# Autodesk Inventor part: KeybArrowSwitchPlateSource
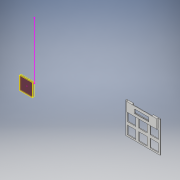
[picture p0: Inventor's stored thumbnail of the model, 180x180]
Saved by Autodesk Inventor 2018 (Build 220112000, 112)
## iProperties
Created: 2017-10
Part Number: KeybArrowSwitchPlateSource
Material: Generic
Document SubType Name: Modeling
Designer: Buddy
Density: 1 g/cm^3
Appearance: Default
Author: Buddy
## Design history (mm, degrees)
sketch "File Was"
  geometry: L1 (222.827, 62.893)-(216.827, 62.893); L2 (168.201, 27.319)-(182.201, 27.319); L3 (182.201, 27.319)-(182.201, 13.32); L4 (182.201, 13.32)-(168.201, 13.32); L5 (168.201, 13.32)-(168.201, 27.319); L6 (187.251, 27.319)-(201.251, 27.319); L7 (201.251, 27.319)-(201.251, 13.32); L8 (201.251, 13.32)-(187.251, 13.32); L9 (187.251, 13.32)-(187.251, 27.319); L10 (206.301, 13.32)-(206.301, 27.319); L11 (220.301, 27.319)-(220.301, 13.32); L12 (220.301, 13.32)-(206.301, 13.32); L13 (206.301, 27.319)-(220.301, 27.319); L14 (201.251, 46.369)-(201.251, 32.37); L15 (206.301, 32.37)-(206.301, 46.369); L16 (220.301, 32.37)-(206.301, 32.37); L17 (206.301, 46.369)-(220.301, 46.369); L18 (220.301, 46.369)-(220.301, 32.37); L19 (222.827, 62.893)-(222.827, 10.794); L20 (222.827, 10.794)-(165.677, 10.794); L21 (168.201, 46.369)-(182.201, 46.369); L22 (182.201, 46.369)-(182.201, 32.37); L23 (187.251, 46.369)-(201.251, 46.369); L24 (201.251, 32.37)-(187.251, 32.37); L25 (187.251, 32.37)-(187.251, 46.369); L26 (182.201, 32.37)-(168.201, 32.37); L27 (168.201, 32.37)-(168.201, 46.369); L28 (165.677, 10.794)-(165.677, 62.893); L29 (165.677, 62.893)-(171.677, 62.893); L30 (165.677, 62.893)-(171.677, 62.893); L31 (216.827, 62.893)-(222.827, 62.893); L32 (222.827, 62.893)-(222.827, 10.794); L33 (222.827, 10.794)-(165.677, 10.794); L34 (165.677, 10.794)-(165.677, 62.893); L35 (168.201, 32.37)-(182.201, 32.37); L36 (182.201, 32.37)-(182.201, 46.369); L37 (182.201, 46.369)-(168.201, 46.369); L38 (168.201, 46.369)-(168.201, 32.37); L39 (187.251, 32.37)-(201.251, 32.37); L40 (201.251, 32.37)-(201.251, 46.369); L41 (201.251, 46.369)-(187.251, 46.369); L42 (187.251, 46.369)-(187.251, 32.37); L43 (206.301, 32.37)-(220.301, 32.37); L44 (220.301, 32.37)-(220.301, 46.369); L45 (220.301, 46.369)-(206.301, 46.369); L46 (206.301, 46.369)-(206.301, 32.37); L47 (168.201, 13.32)-(182.201, 13.32); L48 (182.201, 13.32)-(182.201, 27.319); L49 (182.201, 27.319)-(168.201, 27.319); L50 (168.201, 27.319)-(168.201, 13.32); L51 (187.251, 13.32)-(201.251, 13.32); L52 (201.251, 13.32)-(201.251, 27.319); L53 (201.251, 27.319)-(187.251, 27.319); L54 (187.251, 27.319)-(187.251, 13.32); L55 (206.301, 13.32)-(220.301, 13.32); L56 (220.301, 13.32)-(220.301, 27.319); L57 (220.301, 27.319)-(206.301, 27.319); L58 (206.301, 27.319)-(206.301, 13.32); L59 (171.677, 62.893)-(177.773, 62.893); L60 (177.773, 62.893)-(177.773, 50.758); L61 (216.827, 62.893)-(210.731, 62.893); L62 (210.731, 62.893)-(210.731, 50.758); L63 (210.731, 50.758)-(177.773, 50.758); 1 further point
  constraints: 126 end point, 15 equal length, 10 perpendicular, 8 horizontal
  dimensions: "d5" = 6.096 distance of L30.end L59.end; "d6" = 6.096 distance of L1.end L61.end
node "Created/Designed by:"
sketch "Foster Phillips"
  geometry: L1 (12.663, 105.382)-(12.663, 10.132) reference; 1 further point
node "Instagram: https://www.instagram.com/lego_Rocket_08/"
node "Instructables: https://www.instructables.com/member/FosterP/"
sketch "Sketch4"
  geometry: L1 (177.773, 62.893)-(165.677, 62.893) reference; L2 (177.773, 50.758)-(168.169, 50.758); L3 (168.169, 50.758)-(168.169, 62.893); L4 (168.169, 62.893)-(177.773, 62.893); L5 (177.773, 62.893)-(177.773, 50.758); L6 (210.731, 50.758)-(210.731, 62.893) reference; L7 (210.731, 50.758)-(220.301, 50.758); L8 (220.301, 50.758)-(220.301, 62.893); L9 (220.301, 62.893)-(210.731, 62.893); L10 (210.731, 62.893)-(210.731, 50.758); 1 further point
  constraints: 16 end point, 4 parallel, 2 horizontal, 2 perpendicular, 2 point on line
extrude "Fiverr (For commisions) https://www.fiverr.com/lego_rocket" cut sketch "Sketch4" distance "d11" = 25.4; taper "d12" = 0 deg
node "Im Sorry That the"
sketch "Sketch5"
  geometry: L1 (168.169, 50.758)-(220.301, 50.758) reference; L2 (168.169, 50.758)-(168.169, 47.758); L3 (194.235, 50.758)-(194.235, 47.758); L4 (194.235, 47.758)-(219.635, 47.758); L5 (219.635, 47.758)-(219.635, 62.893); L6 (219.635, 62.893)-(194.235, 62.893); L7 (194.235, 62.893)-(194.235, 47.758); L8 (194.235, 62.893)-(168.835, 62.893); L9 (168.835, 62.893)-(168.835, 47.758); L10 (168.835, 47.758)-(194.235, 47.758); L11 (194.235, 47.758)-(194.235, 62.893); 1 further point
  constraints: 20 end point, 4 parallel, 2 horizontal, 2 perpendicular, 2 vertical, 1 midpoint, 1 point on line
  dimensions: "d13" = 3 distance of L1.start L2.end; "d14" = 25.4 distance of L6.end L5.end; "d15" = 25.4 distance of L10.end L9.end
extrude "Source file is weird" join sketch "Sketch5" distance "d16" = 2; taper "d17" = 0 deg
node "But I had to delete other stuff"
sketch "Sketch6"
  geometry: L1 (-222.827, 62.893)-(-220.301, 62.893) reference; L2 (-219.635, 50.758)-(-168.835, 50.758) reference; L3 (-220.301, 62.893)-(-218.293, 62.893); L4 (-218.293, 62.893)-(-218.293, 50.758); L5 (-218.293, 50.758)-(-220.301, 50.758); L6 (-220.301, 50.758)-(-220.301, 62.893); L7 (-168.169, 50.758)-(-168.169, 62.893) reference; L8 (-168.169, 62.893)-(-170.169, 62.893); L9 (-170.169, 62.893)-(-170.169, 50.758); L10 (-170.169, 50.758)-(-168.169, 50.758); L11 (-168.169, 50.758)-(-168.169, 62.893); 1 further point
  constraints: 16 end point, 4 parallel, 2 horizontal, 2 perpendicular, 2 point on line
  dimensions: "d18" = 2 distance of L10.end L9.end
extrude "Because it was uneccesary" join sketch "Sketch6" distance "d19" = 1.3; taper "d20" = 0 deg
node "and I didn't want other people having it"
sketch "Sketch7"
  geometry: L1 (218.293, 62.893)-(170.169, 62.893) reference; L2 (194.231, 62.893)-(194.235, 47.758); L3 (219.635, 47.758)-(168.835, 47.758) reference; L4 (180.733, 49.326)-(207.733, 49.326); L5 (207.733, 49.326)-(207.733, 61.326); L6 (207.733, 61.326)-(180.733, 61.326); L7 (180.733, 61.326)-(180.733, 49.326); L8 (180.733, 49.326)-(207.733, 61.326); L9 (207.733, 49.326)-(180.733, 61.326); L10 (207.733, 61.326)-(214.233, 61.326); L11 (214.233, 61.326)-(214.233, 49.326); L12 (214.233, 49.326)-(207.733, 49.326); L13 (207.733, 49.326)-(207.733, 61.326); 2 further points
  constraints: 22 end point, 5 midpoint, 4 parallel, 2 horizontal, 2 perpendicular
  dimensions: "d21" = 27 distance of L6.end L5.end; "d22" = 12 distance of L5.end L4.end; "d23" = 6.5 distance of L11.end L12.end; "d24" = 12 distance of L10.end L11.end
extrude "(Sorry)" cut sketch "Sketch7" distance "d25" = 76.2; taper "d26" = 0 deg
node "but, My Design, I do what I want"
sketch "Sketch8"
  geometry: L1 (214.233, 49.326)-(180.733, 49.326) reference; L2 (214.233, 61.326)-(214.233, 49.326) reference; L3 (180.733, 49.326)-(214.233, 49.326); L4 (214.233, 49.326)-(214.233, 61.326); L5 (214.233, 61.326)-(180.733, 61.326); L6 (180.733, 61.326)-(180.733, 49.326); 1 further point
  constraints: 8 end point, 2 parallel, 1 horizontal, 1 perpendicular
extrude "Extrusion9" join sketch "Sketch8" distance "d27" = 1; taper "d28" = 0 deg
workplane "Work Plane16"
sketch "Sketch9"
  geometry: L1 (-218.293, 50.758)-(-214.233, 50.758) reference; L2 (-218.293, 50.758)-(-170.169, 50.758); L3 (-170.169, 50.758)-(-170.169, 48.724); L4 (-170.169, 48.724)-(-218.293, 48.724); L5 (-218.293, 48.724)-(-218.293, 50.758); 1 further point
  constraints: 8 end point, 2 parallel, 1 horizontal, 1 perpendicular
extrude "Extrusion10" cut sketch "Sketch9" distance "d29" = 1.3; taper "d30" = 0 deg
workplane "Work Plane17"
sketch "Sketch10"
  geometry: L1 (-218.293, 62.893)-(-170.169, 62.893) reference; L2 (-194.231, 62.893)-(-194.231, 48.724); L3 (-170.169, 48.724)-(-218.293, 48.724) reference; L4 (-180.733, 61.326)-(-180.733, 49.326) reference; L5 (-180.733, 55.326)-(-194.231, 55.326); L6 (-206.106, 51.951)-(-182.356, 51.951); L7 (-182.356, 51.951)-(-182.356, 58.701); L8 (-182.356, 58.701)-(-206.106, 58.701); L9 (-206.106, 58.701)-(-206.106, 51.951); L10 (-206.106, 51.951)-(-182.356, 58.701); L11 (-182.356, 51.951)-(-206.106, 58.701); 1 further point
  constraints: 16 end point, 5 midpoint, 2 parallel, 2 perpendicular, 1 horizontal, 1 point on line
  dimensions: "d31" = 23.75 distance of L8.end L7.end; "d32" = 6.75 distance of L7.end L6.end
extrude "Extrusion11" cut sketch "Sketch10" distance "d33" = 1.3; taper "d34" = 0 deg
workplane "Work Plane19"
sketch "Sketch11"
  geometry: L1 (-214.233, 61.326)-(-180.733, 61.326) reference; L2 (-180.733, 61.326)-(-180.733, 49.326) reference; L3 (-214.233, 61.326)-(-180.733, 61.326); L4 (-180.733, 61.326)-(-180.733, 49.326); L5 (-180.733, 49.326)-(-214.233, 49.326); L6 (-214.233, 49.326)-(-214.233, 61.326); 1 further point
  constraints: 8 end point, 2 parallel, 1 horizontal, 1 perpendicular
extrude "Extrusion12" cut sketch "Sketch11" distance "d35" = 0.2; taper "d36" = 0 deg
extrude "Extrusion13" join sketch "File Was" distance "d37" = 1.3; taper "d38" = 0 deg
sketch "Sketch12"
  geometry: L1 (-214.233, 61.326)-(-180.733, 61.326) reference; L2 (-180.733, 61.326)-(-210.731, 61.326); L3 (-210.731, 61.326)-(-210.731, 62.893); L4 (-210.731, 62.893)-(-180.733, 62.893); L5 (-180.733, 62.893)-(-180.733, 61.326); L6 (-180.733, 61.326)-(-180.733, 50.758) reference; L7 (-177.773, 50.758)-(-177.773, 62.893) reference; L8 (-180.733, 61.326)-(-177.773, 61.326); L9 (-177.773, 61.326)-(-177.773, 62.893); L10 (-177.773, 62.893)-(-180.733, 62.893); L11 (-180.733, 62.893)-(-180.733, 61.326); 1 further point
  constraints: 16 end point, 4 parallel, 2 horizontal, 2 perpendicular
extrude "Extrusion14" cut sketch "Sketch12" distance "d39" = 1.2; taper "d40" = 0 deg
sketch "Sketch13"
  geometry: L1 (29.998, 0)-(29.998, 1.2) reference; L2 (29.998, 1.2)-(0, 1.2) reference; L3 (29.998, 0)-(0, 0); L4 (0, 0)-(0, 1.2); L5 (0, 1.2)-(29.998, 1.2); L6 (29.998, 1.2)-(29.998, 0); 1 further point
  constraints: 8 end point, 2 parallel, 1 horizontal, 1 perpendicular
extrude "Extrusion15" join sketch "Sketch13" distance "d41" = 1.4; taper "d42" = 0 deg
body "Solid1"
